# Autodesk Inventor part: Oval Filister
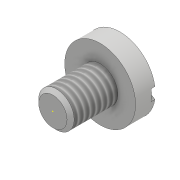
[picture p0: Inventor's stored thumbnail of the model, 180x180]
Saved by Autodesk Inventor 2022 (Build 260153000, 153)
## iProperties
Created: 2016-06
Part Number: Oval Filister
Material: Generic
Document SubType Name: Modeling
Designer: CADCIM
Density: 1 g/cm^3
Appearance: Default
Mass: 0.639925 g
Surface Area: 5.32794 cm^2
Volume: 0.639925 cm^3
Author: CADCIM
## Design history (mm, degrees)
sketch "Sketch1"
  geometry: 1 further point
sketch "Sketch2"
  geometry: C1 r 3 at (0, 0); 1 further point
  constraints: 1 centre point, 1 coincident
  dimensions: "d0" = 6 diameter of C1
extrude "Extrusion1" new body sketch "Sketch2" distance "d1" = 8; taper "d2" = 0 deg
sketch "Sketch3"
  geometry: 1 further point
sketch "Sketch4"
  geometry: L1 (8, 0)-(8, -6); L2 (8, -3)-(8, 3) reference; L3 (8, -6)-(11.35, -6); L4 (12.6, 0)-(8, 0); A1 r 15.025 centre (-2.425, 0) between (11.35, -6) and (12.6, 0); 2 further points
  constraints: 6 end point, 2 midpoint, 2 point on circle, 1 centre point, 1 horizontal, 1 horizontal alignment, 1 perpendicular, 1 point on line, 1 vertical
  dimensions: "d3" = 6 distance of L1.start L1.end; "d4" = 4.6 distance of L4.start L1.start; "d5" = 1.25 horizontal distance of L3.end L4.start
revolve "Revolution1" sketch "Sketch4" stored, may be unused: angle "d6" = 90 deg
workplane "Work Plane1"
sketch "Sketch5"
  geometry: L1 (6.611, -0.95)-(-6.611, -0.95); L2 (-6.611, -0.95)-(-6.611, 0.95); L3 (-6.611, 0.95)-(6.611, 0.95); L4 (6.611, 0.95)-(6.611, -0.95); L5 (6.611, 0)-(-6.611, 0); 2 further points
  constraints: 10 end point, 3 midpoint, 2 parallel, 1 coincident, 1 horizontal, 1 perpendicular
  dimensions: "d8" = 1.9 distance of L3.end L1.start
extrude "Extrusion2" cut sketch "Sketch5" distance "d9" = 1.9; taper "d10" = 0 deg
thread "Thread1" dims "d11" = 10, "d12" = 0
chamfer "Chamfer1" distance "d13" = 0.6; stored, may be unused: second distance "d14" = 2, angle "d15" = 45 deg
body "Solid1"
other parameters: "d7" = -4.6
